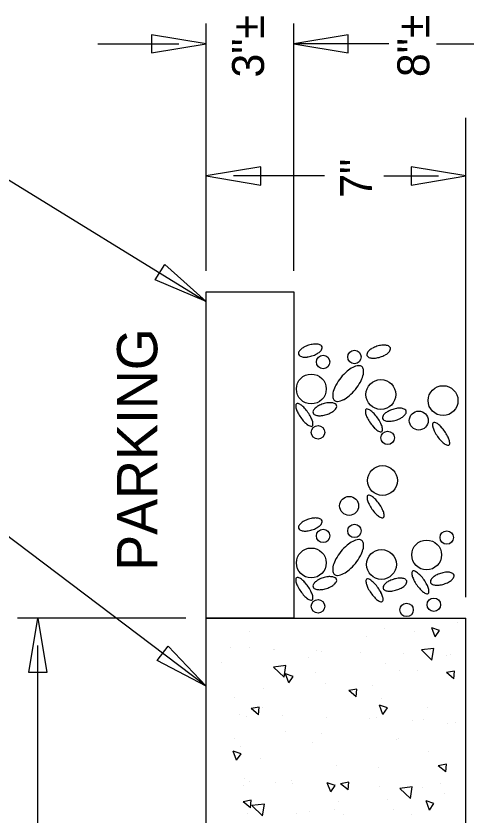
# Model space of a CAD drawing. Extents: x 0 to 8.5, y 0 to 11.
# Drawn here: x 4.503 to 5.35, y 8.342 to 9.844 of the extents above; entities that cross this region are included whole.
import ezdxf

# ---------------------------------------------------------------- set-up
doc = ezdxf.new("R2010")
doc.units = 0
for name, color, linetype in [('Default', 7, 'Continuous'), ('DTL-ASPHALT', 7, 'Continuous'), ('DTL-CONCRETE', 7, 'Continuous'), ('DTL-GRAVEL', 7, 'Continuous'), ('DTL-TEXT', 7, 'Continuous'), ('Old_Level_11', 7, 'Continuous')]:
    doc.layers.add(name, color=color, linetype=linetype)

# ---------------------------------------------------------------- blocks, each defined once
blk = doc.blocks.new('POINT_DISPLAY')
at = {"layer": 'Default'}
blk.add_line((0, 0), (0, 0), dxfattribs=at)

msp = doc.modelspace()

# ---------------------------------------------------------------- linework, layer by layer
at = {"layer": 'DTL-ASPHALT'}
for p, q in [((4.8601, 9.3654), (4.8601, 9.6147)), ((4.8601, 8.7137), (4.8601, 9.326))]:
    msp.add_line(p, q, dxfattribs=at)
msp.add_lwpolyline([(5.0244, 8.7137), (4.8601, 8.7137), (4.8601, 9.326), (5.0244, 9.326)], close=True, dxfattribs=at)
at = {"layer": 'DTL-CONCRETE'}
for p, q in [((4.8601, 8.7137), (5.1523, 8.7137)), ((4.8601, 7.0579), (4.8601, 8.7137)), ((5.1523, 8.7137), (5.3471, 8.7137)), ((5.3471, 7.6362), (5.3471, 8.7137)), ((5.29, 8.6783), (5.2834, 8.6953)), ((5.2981, 8.6904), (5.2834, 8.6953)), ((5.3322, 8.7055), (5.3322, 8.7055)), ((4.9423, 8.6883), (4.9423, 8.6883)), ((5.1604, 8.6798), (5.1604, 8.6798)), ((5.1948, 8.6936), (5.1948, 8.6936)), ((5.2506, 8.6876), (5.2506, 8.6876)), ((5.29, 8.6783), (5.2981, 8.6904)), ((4.9059, 8.6583), (4.9059, 8.6583)), ((4.9411, 8.6594), (4.9411, 8.6594)), ((4.9869, 8.6553), (4.9869, 8.6553)), ((4.9884, 8.6548), (4.9884, 8.6548)), ((5.068, 8.6524), (5.068, 8.6524)), ((5.0765, 8.6517), (5.0765, 8.6517)), ((5.1491, 8.6494), (5.1491, 8.6494)), ((5.2871, 8.6567), (5.2639, 8.654)), ((5.2837, 8.635), (5.2639, 8.654)), ((5.2837, 8.635), (5.2871, 8.6567)), ((5.0519, 8.6393), (5.0519, 8.6393)), ((5.2301, 8.6464), (5.2301, 8.6464)), ((5.3112, 8.6435), (5.3112, 8.6435)), ((5.3186, 8.6451), (5.3186, 8.6451)), ((4.8888, 8.63), (4.8888, 8.63)), ((5.0096, 8.6244), (4.9864, 8.6217)), ((5.0062, 8.6027), (4.9864, 8.6217)), ((5.0062, 8.6027), (5.0096, 8.6244)), ((5.1972, 8.6293), (5.1972, 8.6293)), ((5.0153, 8.5922), (5.0088, 8.6092)), ((5.0235, 8.6043), (5.0088, 8.6092)), ((5.0153, 8.5922), (5.0235, 8.6043)), ((5.0649, 8.611), (5.0649, 8.611)), ((5.2221, 8.6149), (5.2221, 8.6149)), ((5.2564, 8.6158), (5.2564, 8.6158)), ((5.3261, 8.6141), (5.3109, 8.6113)), ((5.3249, 8.5995), (5.3109, 8.6113)), ((5.3249, 8.5995), (5.3261, 8.6141)), ((5.0845, 8.5907), (5.0845, 8.5907)), ((4.9683, 8.5808), (4.9683, 8.5808)), ((5.143, 8.5803), (5.1277, 8.5775)), ((5.1417, 8.5657), (5.1277, 8.5775)), ((5.1417, 8.5657), (5.143, 8.5803)), ((5.1725, 8.5876), (5.1725, 8.5876)), ((4.9127, 8.565), (4.9127, 8.565)), ((5.1893, 8.5636), (5.1893, 8.5636)), ((4.9598, 8.5465), (4.9445, 8.5437)), ((4.9585, 8.532), (4.9598, 8.5465)), ((4.9666, 8.5463), (4.9666, 8.5463)), ((5.1919, 8.5329), (5.1854, 8.55)), ((5.2001, 8.5451), (5.1854, 8.55)), ((5.1919, 8.5329), (5.2001, 8.5451)), ((5.275, 8.5456), (5.275, 8.5456)), ((4.923, 8.5333), (4.923, 8.5333)), ((4.9356, 8.5295), (4.9356, 8.5295)), ((4.9585, 8.532), (4.9445, 8.5437)), ((5.0041, 8.5303), (5.0041, 8.5303)), ((5.0851, 8.5273), (5.0851, 8.5273)), ((5.1662, 8.5244), (5.1662, 8.5244)), ((5.1805, 8.5267), (5.1805, 8.5267)), ((5.2473, 8.5214), (5.2473, 8.5214)), ((5.2686, 8.5236), (5.2686, 8.5236)), ((5.3131, 8.5151), (5.3131, 8.5151)), ((5.3283, 8.5184), (5.3283, 8.5184)), ((5.0087, 8.501), (5.0087, 8.501)), ((4.9132, 8.488), (4.9132, 8.488)), ((5.0762, 8.4973), (5.0762, 8.4973)), ((5.2166, 8.4849), (5.2166, 8.4849)), ((5.2215, 8.4873), (5.2215, 8.4873)), ((4.9248, 8.4728), (4.9248, 8.4728)), ((5.0594, 8.481), (5.0594, 8.481)), ((4.9173, 8.4468), (4.9108, 8.4639)), ((4.9255, 8.459), (4.9108, 8.4639)), ((4.9173, 8.4468), (4.9255, 8.4589)), ((5.2766, 8.4626), (5.2766, 8.4626)), ((4.9629, 8.4508), (4.9629, 8.4508)), ((5.3109, 8.4394), (5.2956, 8.4366)), ((5.3096, 8.4249), (5.3109, 8.4394)), ((5.1047, 8.4369), (5.1047, 8.4369)), ((5.1838, 8.4336), (5.1838, 8.4336)), ((5.3096, 8.4249), (5.2956, 8.4366)), ((4.8602, 8.4097), (4.8602, 8.4097)), ((4.9328, 8.4119), (4.9328, 8.4119)), ((4.9301, 8.3995), (4.9301, 8.3995)), ((4.9413, 8.4068), (4.9413, 8.4068)), ((4.991, 8.4043), (4.991, 8.4043)), ((5.0208, 8.4088), (5.0208, 8.4088)), ((5.0223, 8.4038), (5.0223, 8.4038)), ((5.0939, 8.3876), (5.0873, 8.4046)), ((5.1021, 8.3997), (5.0873, 8.4046)), ((5.0939, 8.3876), (5.102, 8.3997)), ((5.1034, 8.4009), (5.1034, 8.4009)), ((5.1277, 8.4056), (5.1124, 8.4028)), ((5.1264, 8.3911), (5.1124, 8.4028)), ((5.1264, 8.3911), (5.1277, 8.4056)), ((5.1845, 8.3979), (5.1845, 8.3979)), ((5.2468, 8.3968), (5.2236, 8.3941)), ((5.2434, 8.3751), (5.2236, 8.3941)), ((5.2434, 8.3751), (5.2468, 8.3968)), ((5.2655, 8.3949), (5.2655, 8.3949)), ((5.2994, 8.4036), (5.2994, 8.4036)), ((5.3076, 8.3851), (5.3076, 8.3851)), ((5.3466, 8.392), (5.3466, 8.392)), ((4.9445, 8.3719), (4.9293, 8.369)), ((4.9432, 8.3573), (4.9293, 8.369)), ((4.9432, 8.3573), (4.9445, 8.3719)), ((4.9693, 8.3645), (4.9461, 8.3618)), ((4.9659, 8.3428), (4.9693, 8.3645)), ((5.2008, 8.3729), (5.2008, 8.3729)), ((5.2794, 8.3533), (5.2729, 8.3704)), ((5.2876, 8.3655), (5.2729, 8.3704)), ((5.2794, 8.3533), (5.2876, 8.3655)), ((4.9659, 8.3428), (4.9461, 8.3618)), ((5.0539, 8.351), (5.0539, 8.351)), ((5.1006, 8.3553), (5.1006, 8.3553)), ((5.2111, 8.3549), (5.2111, 8.3549)), ((4.9376, 8.346), (4.9376, 8.346)), ((5.0289, 8.3478), (5.0289, 8.3478)), ((5.1169, 8.3447), (5.1169, 8.3447)), ((5.2459, 8.3452), (5.2459, 8.3452))]:
    msp.add_line(p, q, dxfattribs=at)
at = {"layer": 'DTL-GRAVEL'}
for centre, radius in [((5.0795, 9.1944), 0.0126), ((5.1383, 9.2038), 0.0126), ((5.0574, 9.1437), 0.028), ((5.188, 9.1334), 0.028), ((5.3046, 9.1219), 0.028), ((5.259, 9.0844), 0.0178), ((5.07, 9.0623), 0.0126), ((5.2006, 9.052), 0.0126), ((5.191, 8.9718), 0.028), ((5.1284, 8.9243), 0.0178), ((5.1383, 8.8773), 0.0126), ((5.0795, 8.8679), 0.0126), ((5.3115, 8.8649), 0.0126), ((5.2738, 8.8322), 0.028), ((5.0574, 8.8172), 0.028), ((5.189, 8.8144), 0.028), ((5.07, 8.7358), 0.0126), ((5.2362, 8.729), 0.0126), ((5.2873, 8.7388), 0.0126)]:
    msp.add_circle(centre, radius, dxfattribs=at)
for centre, radius, start, end in [((5.058, 9.1954), 0.0304, 118.2722, 132.0822), ((5.0676, 9.1776), 0.0506, 107.5826, 118.2722), ((5.0676, 9.1776), 0.0506, 96.893, 107.5826), ((5.0652, 9.1977), 0.0304, 83.0831, 96.893), ((5.0668, 9.2113), 0.0167, 59.8512, 83.0831), ((5.0726, 9.2212), 0.0052, 17.5826, 59.8512), ((5.0726, 9.2212), 0.0052, 335.3141, 17.5826), ((5.1863, 9.1934), 0.0304, 118.2722, 132.0822), ((5.1959, 9.1756), 0.0506, 107.5826, 118.2722), ((5.1959, 9.1756), 0.0506, 96.893, 107.5826), ((5.1935, 9.1957), 0.0304, 83.0831, 96.893), ((5.1951, 9.2093), 0.0167, 59.8512, 83.0831), ((5.2009, 9.2192), 0.0052, 17.5826, 59.8512), ((5.2009, 9.2192), 0.0052, 335.3141, 17.5826), ((5.0384, 9.2104), 0.0052, 155.3141, 197.5826), ((5.0384, 9.2104), 0.0052, 197.5826, 239.8512), ((5.0488, 9.2056), 0.0167, 132.0822, 155.3141), ((5.0442, 9.2203), 0.0167, 239.8512, 263.0831), ((5.0434, 9.254), 0.0506, 276.893, 287.5826), ((5.0434, 9.254), 0.0506, 287.5826, 298.2722), ((5.053, 9.2362), 0.0304, 298.2722, 312.0822), ((5.0622, 9.226), 0.0167, 312.0822, 335.3141), ((5.1667, 9.2084), 0.0052, 155.3141, 197.5826), ((5.1667, 9.2084), 0.0052, 197.5826, 239.8512), ((5.1771, 9.2036), 0.0167, 132.0822, 155.3141), ((5.1717, 9.252), 0.0506, 287.5826, 298.2722), ((5.1813, 9.2342), 0.0304, 298.2722, 312.0822), ((5.1905, 9.224), 0.0167, 312.0822, 335.3141), ((5.0458, 9.2339), 0.0304, 263.0831, 276.893), ((5.1725, 9.2183), 0.0167, 239.8512, 263.0831), ((5.1741, 9.232), 0.0304, 263.0831, 276.893), ((5.1717, 9.252), 0.0506, 276.893, 287.5826), ((5.1868, 9.1051), 0.0951, 130.9175, 140.9829), ((5.1612, 9.1347), 0.056, 117.7861, 130.9175), ((5.1489, 9.1579), 0.0297, 95.0094, 117.7861), ((5.1471, 9.1793), 0.00824, 50.9829, 95.0094), ((5.1471, 9.1793), 0.00824, 6.9564, 50.9829), ((5.1258, 9.1767), 0.0297, 344.1797, 6.9564), ((5.1868, 9.1051), 0.0951, 140.9829, 151.0483), ((5.1005, 9.1839), 0.056, 331.0483, 344.1797), ((5.1526, 9.124), 0.056, 151.0483, 164.1797), ((5.0662, 9.2028), 0.0951, 320.9829, 331.0483), ((5.1273, 9.1312), 0.0297, 164.1797, 186.9564), ((5.0919, 9.1732), 0.056, 297.7861, 310.9175), ((5.0662, 9.2028), 0.0951, 310.9175, 320.9829), ((5.0315, 9.1133), 0.00323, 125.0965, 176.964), ((5.0315, 9.1133), 0.00323, 73.2289, 125.0965), ((5.0266, 9.097), 0.0203, 53.1091, 73.2289), ((5.0948, 9.0676), 0.0506, 107.5826, 118.2722), ((5.0948, 9.0676), 0.0506, 96.893, 107.5826), ((5.0924, 9.0876), 0.0304, 83.0831, 96.893), ((5.094, 9.1013), 0.0167, 59.8512, 83.0831), ((5.106, 9.1286), 0.00824, 186.9564, 230.9829), ((5.106, 9.1286), 0.00824, 230.9829, 275.0094), ((5.0998, 9.1112), 0.0052, 17.5826, 59.8512), ((5.1041, 9.15), 0.0297, 275.0094, 297.7861), ((5.0485, 9.1124), 0.0203, 176.964, 197.0838), ((5.0705, 9.1191), 0.0432, 197.0838, 207.4256), ((5.0128, 9.0786), 0.0432, 42.7673, 53.1091), ((4.9869, 9.0547), 0.0785, 35.0965, 42.7673), ((4.9869, 9.0547), 0.0785, 27.4256, 35.0965), ((5.0656, 9.1003), 0.0052, 155.3141, 197.5826), ((5.076, 9.0955), 0.0167, 132.0822, 155.3141), ((5.0852, 9.0854), 0.0304, 118.2722, 132.0822), ((5.0802, 9.1261), 0.0304, 298.2722, 312.0822), ((5.0894, 9.116), 0.0167, 312.0822, 335.3141), ((5.0998, 9.1112), 0.0052, 335.3141, 17.5826), ((5.1621, 9.103), 0.00323, 125.0965, 176.964), ((5.1791, 9.1021), 0.0203, 176.964, 197.0838), ((5.1621, 9.103), 0.00323, 73.2289, 125.0965), ((5.1572, 9.0866), 0.0203, 53.1091, 73.2289), ((5.1434, 9.0683), 0.0432, 42.7673, 53.1091), ((5.2158, 9.075), 0.0304, 118.2722, 132.0822), ((5.2254, 9.0572), 0.0506, 107.5826, 118.2722), ((5.2254, 9.0572), 0.0506, 96.893, 107.5826), ((5.223, 9.0773), 0.0304, 83.0831, 96.893), ((5.2246, 9.0909), 0.0167, 59.8512, 83.0831), ((5.2304, 9.1008), 0.0052, 17.5826, 59.8512), ((5.2304, 9.1008), 0.0052, 335.3141, 17.5826), ((5.1018, 9.1354), 0.0785, 207.4256, 215.0965), ((5.1018, 9.1354), 0.0785, 215.0965, 222.7673), ((5.0182, 9.0709), 0.0432, 17.0838, 27.4256), ((5.0656, 9.1003), 0.0052, 197.5826, 239.8512), ((5.0714, 9.1103), 0.0167, 239.8512, 263.0831), ((5.073, 9.1239), 0.0304, 263.0831, 276.893), ((5.0706, 9.144), 0.0506, 276.893, 287.5826), ((5.0706, 9.144), 0.0506, 287.5826, 298.2722), ((5.2011, 9.1088), 0.0432, 197.0838, 207.4256), ((5.2324, 9.125), 0.0785, 207.4256, 215.0965), ((5.1175, 9.0443), 0.0785, 35.0965, 42.7673), ((5.1175, 9.0443), 0.0785, 27.4256, 35.0965), ((5.1962, 9.09), 0.0052, 155.3141, 197.5826), ((5.1962, 9.09), 0.0052, 197.5826, 239.8512), ((5.2066, 9.0852), 0.0167, 132.0822, 155.3141), ((5.202, 9.0999), 0.0167, 239.8512, 263.0831), ((5.2012, 9.1336), 0.0506, 276.893, 287.5826), ((5.2012, 9.1336), 0.0506, 287.5826, 298.2722), ((5.2108, 9.1158), 0.0304, 298.2722, 312.0822), ((5.22, 9.1056), 0.0167, 312.0822, 335.3141), ((5.0759, 9.1114), 0.0432, 222.7673, 233.1091), ((5.0621, 9.0931), 0.0203, 233.1091, 253.2289), ((5.0572, 9.0768), 0.00323, 253.2289, 305.0965), ((5.0572, 9.0768), 0.00323, 305.0965, 356.964), ((5.0402, 9.0777), 0.0203, 356.964, 17.0838), ((5.2324, 9.125), 0.0785, 215.0965, 222.7673), ((5.2065, 9.1011), 0.0432, 222.7673, 233.1091), ((5.1488, 9.0606), 0.0432, 17.0838, 27.4256), ((5.1708, 9.0673), 0.0203, 356.964, 17.0838), ((5.2036, 9.1135), 0.0304, 263.0831, 276.893), ((5.3051, 9.0768), 0.0203, 176.964, 197.0838), ((5.2881, 9.0777), 0.00323, 125.0965, 176.964), ((5.3271, 9.0836), 0.0432, 197.0838, 207.4256), ((5.2881, 9.0777), 0.00323, 73.2289, 125.0965), ((5.2832, 9.0614), 0.0203, 53.1091, 73.2289), ((5.2694, 9.043), 0.0432, 42.7673, 53.1091), ((5.2435, 9.0191), 0.0785, 35.0965, 42.7673), ((5.1927, 9.0827), 0.0203, 233.1091, 253.2289), ((5.1878, 9.0664), 0.00323, 253.2289, 305.0965), ((5.1878, 9.0664), 0.00323, 305.0965, 356.964), ((5.3584, 9.0998), 0.0785, 207.4256, 215.0965), ((5.2435, 9.0191), 0.0785, 27.4256, 35.0965), ((5.2748, 9.0353), 0.0432, 17.0838, 27.4256), ((5.3584, 9.0998), 0.0785, 215.0965, 222.7673), ((5.3325, 9.0758), 0.0432, 222.7673, 233.1091), ((5.3187, 9.0575), 0.0203, 233.1091, 253.2289), ((5.3138, 9.0412), 0.00323, 305.0965, 356.964), ((5.2968, 9.0421), 0.0203, 356.964, 17.0838), ((5.3138, 9.0412), 0.00323, 253.2289, 305.0965), ((5.1652, 8.9414), 0.00323, 125.0965, 176.964), ((5.1822, 8.9405), 0.0203, 176.964, 197.0838), ((5.1652, 8.9414), 0.00323, 73.2289, 125.0965), ((5.1602, 8.9251), 0.0203, 53.1091, 73.2289), ((5.1465, 8.9067), 0.0432, 42.7673, 53.1091), ((5.1206, 8.8828), 0.0785, 35.0965, 42.7673), ((5.2041, 8.9473), 0.0432, 197.0838, 207.4256), ((5.2354, 8.9635), 0.0785, 207.4256, 215.0965), ((5.1206, 8.8828), 0.0785, 27.4256, 35.0965), ((5.2354, 8.9635), 0.0785, 215.0965, 222.7673), ((5.2095, 8.9396), 0.0432, 222.7673, 233.1091), ((5.1958, 8.9212), 0.0203, 233.1091, 253.2289), ((5.1519, 8.899), 0.0432, 17.0838, 27.4256), ((5.1908, 8.9049), 0.00323, 305.0965, 356.964), ((5.1738, 8.9058), 0.0203, 356.964, 17.0838), ((5.0488, 8.8791), 0.0167, 132.0822, 155.3141), ((5.058, 8.8689), 0.0304, 118.2722, 132.0822), ((5.0676, 8.8511), 0.0506, 107.5826, 118.2722), ((5.0676, 8.8511), 0.0506, 96.893, 107.5826), ((5.0652, 8.8712), 0.0304, 83.0831, 96.893), ((5.0668, 8.8848), 0.0167, 59.8512, 83.0831), ((5.0622, 8.8995), 0.0167, 312.0822, 335.3141), ((5.0726, 8.8947), 0.0052, 17.5826, 59.8512), ((5.0726, 8.8947), 0.0052, 335.3141, 17.5826), ((5.1908, 8.9049), 0.00323, 253.2289, 305.0965), ((5.0384, 8.8839), 0.0052, 155.3141, 197.5826), ((5.0384, 8.8839), 0.0052, 197.5826, 239.8512), ((5.0442, 8.8938), 0.0167, 239.8512, 263.0831), ((5.0458, 8.9074), 0.0304, 263.0831, 276.893), ((5.0434, 8.9275), 0.0506, 276.893, 287.5826), ((5.0434, 8.9275), 0.0506, 287.5826, 298.2722), ((5.053, 8.9097), 0.0304, 298.2722, 312.0822), ((5.1489, 8.8314), 0.0297, 95.0094, 117.7861), ((5.1471, 8.8528), 0.00824, 50.9829, 95.0094), ((5.1868, 8.7786), 0.0951, 130.9175, 140.9829), ((5.1612, 8.8082), 0.056, 117.7861, 130.9175), ((5.1471, 8.8528), 0.00824, 6.9564, 50.9829), ((5.1258, 8.8502), 0.0297, 344.1797, 6.9564), ((5.1868, 8.7786), 0.0951, 140.9829, 151.0483), ((5.0662, 8.8763), 0.0951, 320.9829, 331.0483), ((5.1005, 8.8574), 0.056, 331.0483, 344.1797), ((5.1526, 8.7975), 0.056, 151.0483, 164.1797), ((5.0662, 8.8763), 0.0951, 310.9175, 320.9829), ((5.1273, 8.8047), 0.0297, 164.1797, 186.9564), ((5.106, 8.8021), 0.00824, 186.9564, 230.9829), ((5.0919, 8.8467), 0.056, 297.7861, 310.9175), ((5.2492, 8.799), 0.00323, 125.0965, 176.964), ((5.2492, 8.799), 0.00323, 73.2289, 125.0965), ((5.2443, 8.7827), 0.0203, 53.1091, 73.2289), ((5.3152, 8.7494), 0.0506, 96.893, 107.5826), ((5.3128, 8.7695), 0.0304, 83.0831, 96.893), ((5.3145, 8.7831), 0.0167, 59.8512, 83.0831), ((5.0485, 8.7859), 0.0203, 176.964, 197.0838), ((5.0315, 8.7868), 0.00323, 125.0965, 176.964), ((5.0315, 8.7868), 0.00323, 73.2289, 125.0965), ((5.0266, 8.7705), 0.0203, 53.1091, 73.2289), ((5.0128, 8.7521), 0.0432, 42.7673, 53.1091), ((5.0852, 8.7589), 0.0304, 118.2722, 132.0822), ((5.0948, 8.7411), 0.0506, 107.5826, 118.2722), ((5.0948, 8.7411), 0.0506, 96.893, 107.5826), ((5.0924, 8.7611), 0.0304, 83.0831, 96.893), ((5.094, 8.7748), 0.0167, 59.8512, 83.0831), ((5.106, 8.8021), 0.00824, 230.9829, 275.0094), ((5.0998, 8.7847), 0.0052, 17.5826, 59.8512), ((5.0998, 8.7847), 0.0052, 335.3141, 17.5826), ((5.1041, 8.8235), 0.0297, 275.0094, 297.7861), ((5.1631, 8.784), 0.00323, 125.0965, 176.964), ((5.1631, 8.784), 0.00323, 73.2289, 125.0965), ((5.1582, 8.7677), 0.0203, 53.1091, 73.2289), ((5.2264, 8.7382), 0.0506, 107.5826, 118.2722), ((5.2264, 8.7382), 0.0506, 96.893, 107.5826), ((5.224, 8.7583), 0.0304, 83.0831, 96.893), ((5.2257, 8.772), 0.0167, 59.8512, 83.0831), ((5.2314, 8.7819), 0.0052, 17.5826, 59.8512), ((5.2663, 8.7981), 0.0203, 176.964, 197.0838), ((5.2882, 8.8048), 0.0432, 197.0838, 207.4256), ((5.3195, 8.8211), 0.0785, 207.4256, 215.0965), ((5.2305, 8.7643), 0.0432, 42.7673, 53.1091), ((5.2047, 8.7404), 0.0785, 35.0965, 42.7673), ((5.2047, 8.7404), 0.0785, 27.4256, 35.0965), ((5.2965, 8.7774), 0.0167, 132.0822, 155.3141), ((5.3057, 8.7672), 0.0304, 118.2722, 132.0822), ((5.3152, 8.7494), 0.0506, 107.5826, 118.2722), ((5.3006, 8.808), 0.0304, 298.2722, 312.0822), ((5.3098, 8.7978), 0.0167, 312.0822, 335.3141), ((5.3202, 8.793), 0.0052, 17.5826, 59.8512), ((5.3202, 8.793), 0.0052, 335.3141, 17.5826), ((5.0705, 8.7926), 0.0432, 197.0838, 207.4256), ((5.1018, 8.8089), 0.0785, 207.4256, 215.0965), ((4.9869, 8.7282), 0.0785, 35.0965, 42.7673), ((4.9869, 8.7282), 0.0785, 27.4256, 35.0965), ((5.0656, 8.7738), 0.0052, 155.3141, 197.5826), ((5.0656, 8.7738), 0.0052, 197.5826, 239.8512), ((5.076, 8.769), 0.0167, 132.0822, 155.3141), ((5.0706, 8.8175), 0.0506, 287.5826, 298.2722), ((5.0802, 8.7996), 0.0304, 298.2722, 312.0822), ((5.0894, 8.7895), 0.0167, 312.0822, 335.3141), ((5.1802, 8.7831), 0.0203, 176.964, 197.0838), ((5.2021, 8.7898), 0.0432, 197.0838, 207.4256), ((5.2334, 8.8061), 0.0785, 207.4256, 215.0965), ((5.1444, 8.7493), 0.0432, 42.7673, 53.1091), ((5.1185, 8.7254), 0.0785, 35.0965, 42.7673), ((5.1185, 8.7254), 0.0785, 27.4256, 35.0965), ((5.1972, 8.771), 0.0052, 155.3141, 197.5826), ((5.1972, 8.771), 0.0052, 197.5826, 239.8512), ((5.2077, 8.7662), 0.0167, 132.0822, 155.3141), ((5.2168, 8.7561), 0.0304, 118.2722, 132.0822), ((5.2022, 8.8147), 0.0506, 287.5826, 298.2722), ((5.2118, 8.7968), 0.0304, 298.2722, 312.0822), ((5.221, 8.7867), 0.0167, 312.0822, 335.3141), ((5.2314, 8.7819), 0.0052, 335.3141, 17.5826), ((5.3195, 8.8211), 0.0785, 215.0965, 222.7673), ((5.236, 8.7566), 0.0432, 17.0838, 27.4256), ((5.286, 8.7822), 0.0052, 155.3141, 197.5826), ((5.286, 8.7822), 0.0052, 197.5826, 239.8512), ((5.2918, 8.7921), 0.0167, 239.8512, 263.0831), ((5.2935, 8.8057), 0.0304, 263.0831, 276.893), ((5.291, 8.8258), 0.0506, 276.893, 287.5826), ((5.291, 8.8258), 0.0506, 287.5826, 298.2722), ((5.1018, 8.8089), 0.0785, 215.0965, 222.7673), ((5.0759, 8.7849), 0.0432, 222.7673, 233.1091), ((5.0182, 8.7444), 0.0432, 17.0838, 27.4256), ((5.0402, 8.7512), 0.0203, 356.964, 17.0838), ((5.0714, 8.7838), 0.0167, 239.8512, 263.0831), ((5.073, 8.7974), 0.0304, 263.0831, 276.893), ((5.0706, 8.8175), 0.0506, 276.893, 287.5826), ((5.2334, 8.8061), 0.0785, 215.0965, 222.7673), ((5.1498, 8.7416), 0.0432, 17.0838, 27.4256), ((5.203, 8.781), 0.0167, 239.8512, 263.0831), ((5.2046, 8.7946), 0.0304, 263.0831, 276.893), ((5.2022, 8.8147), 0.0506, 276.893, 287.5826), ((5.2936, 8.7971), 0.0432, 222.7673, 233.1091), ((5.2798, 8.7788), 0.0203, 233.1091, 253.2289), ((5.2749, 8.7625), 0.00323, 253.2289, 305.0965), ((5.2749, 8.7625), 0.00323, 305.0965, 356.964), ((5.2579, 8.7634), 0.0203, 356.964, 17.0838), ((5.0621, 8.7666), 0.0203, 233.1091, 253.2289), ((5.0572, 8.7503), 0.00323, 253.2289, 305.0965), ((5.0572, 8.7503), 0.00323, 305.0965, 356.964), ((5.2075, 8.7821), 0.0432, 222.7673, 233.1091), ((5.1937, 8.7638), 0.0203, 233.1091, 253.2289), ((5.1888, 8.7475), 0.00323, 253.2289, 305.0965), ((5.1888, 8.7475), 0.00323, 305.0965, 356.964), ((5.1718, 8.7484), 0.0203, 356.964, 17.0838)]:
    msp.add_arc(centre, radius, start, end, dxfattribs=at)
at = {"layer": 'DTL-TEXT'}
for p, q in [((4.8601, 9.3951), (4.8601, 9.8299)), ((5.0244, 9.3951), (5.0244, 9.8299)), ((5.0244, 9.3654), (5.0244, 9.8299)), ((4.6569, 9.7915), (4.8089, 9.7915)), ((5.0756, 9.7915), (5.0244, 9.7915)), ((5.2028, 9.7915), (5.0756, 9.7915)), ((5.2924, 9.7915), (5.4359, 9.7915)), ((5.3471, 9.3654), (5.3471, 9.6524)), ((4.474, 9.5455), (4.8601, 9.3082)), ((5.0822, 9.5436), (4.9113, 9.5436)), ((5.1932, 9.5436), (5.2959, 9.5436)), ((5.3471, 8.7528), (5.3471, 9.3654)), ((4.8217, 8.7137), (4.5059, 8.7137)), ((4.5443, 8.2475), (4.5443, 8.6625))]:
    msp.add_line(p, q, dxfattribs=at)
for points in [[(4.7577, 9.7744), (4.8601, 9.7915), (4.7577, 9.8085)], [(5.1268, 9.8085), (5.0244, 9.7915), (5.1268, 9.7744)], [(4.9625, 9.5607), (4.8601, 9.5436), (4.9625, 9.5266)], [(5.2447, 9.5266), (5.3471, 9.5436), (5.2447, 9.5607)], [(4.7825, 9.3772), (4.8601, 9.3082), (4.7643, 9.3483)], [(4.5272, 8.6113), (4.5443, 8.7137), (4.5614, 8.6113)], [(4.7886, 8.6612), (4.86, 8.5858), (4.7681, 8.634)]]:
    msp.add_lwpolyline(points, close=True, dxfattribs=at)
msp.add_lwpolyline([(4.86, 8.5858), (4.1976, 9.0867), (4.1976, 9.1701)], dxfattribs=at)

# ---------------------------------------------------------------- block references
at = {"layer": 'DTL-TEXT', "xscale": 0.6400000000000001, "yscale": 0.6400000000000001, "rotation": 90}
msp.add_blockref('POINT_DISPLAY', (5.109, 8.3686), dxfattribs=at)

# ---------------------------------------------------------------- texts
at = {"layer": 'DTL-TEXT'}
for s, p in [('3"±', (4.9687, 9.7284)), ('8"±', (5.2788, 9.7292)), ('7"', (5.1714, 9.5027))]:
    msp.add_text(s, height=0.06, rotation=90, dxfattribs=at).set_placement(p)
at = {"layer": 'Old_Level_11'}
msp.add_text('PARKING', height=0.0756, rotation=90, dxfattribs=at).set_placement((4.7685, 8.8025))

doc.saveas('drawing.dxf')
